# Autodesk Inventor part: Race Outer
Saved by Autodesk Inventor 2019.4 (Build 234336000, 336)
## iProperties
Created: 2020-05
Part Number: Race Outer
Material: Generic
Document SubType Name: Modeling
Designer: Administrator
Density: 1 g/cm^3
Appearance: Default
Title: Race Outer
Author: Administrator
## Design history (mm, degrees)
feature "Body1"
body "Solid1"
